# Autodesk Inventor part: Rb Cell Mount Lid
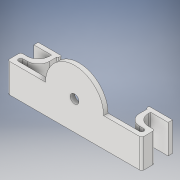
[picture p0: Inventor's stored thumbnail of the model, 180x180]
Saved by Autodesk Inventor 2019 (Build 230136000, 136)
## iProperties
Created: 2019-02
Part Number: Rb Cell Mount Lid
Material: PC/ABS Plastic
Document SubType Name: Modeling
Designer: Rydberg
Density: 0.357273 g/cm^3
Appearance: Smooth - White
Author: Rydberg
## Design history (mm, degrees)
sketch "Sketch1"
  geometry: L1 (0, 0)-(41, 0); L2 (41, 0)-(41, -13.2); L3 (41, -13.2)-(0, -13.2); L4 (0, -13.2)-(0, 0); C1 r 13.2 at (20.5, -13.2)
  constraints: 8 end point, 2 parallel, 1 centre point, 1 horizontal, 1 midpoint, 1 perpendicular
  dimensions: "d0" = 41 distance of L2.end L3.end; "d1" = 13.2 distance of L1.end L2.end; "d2" = 26.4 diameter of C1
extrude "Extrusion1" new body sketch "Sketch1" distance "d3" = 2; taper "d4" = 0 deg
sketch "Sketch2"
  geometry: L1 (41, 0)-(0, 0) reference; L2 (0, 0)-(-2, 0); L3 (-2, 0)-(-2, -13.2); L4 (-2, -13.2)-(0, -13.2); L5 (0, -13.2)-(0, 0); L6 (41, 0)-(43, 0); L7 (43, 0)-(43, -13.2); L8 (43, -13.2)-(41, -13.2); L9 (41, -13.2)-(41, 0)
  constraints: 16 end point, 4 parallel, 2 horizontal, 2 perpendicular, 1 point on line
  dimensions: "d5" = 2 distance of L4.end L3.end; "d6" = 2 distance of L8.end L7.end
extrude "Extrusion2" join sketch "Sketch2" distance "d7" = 12.5; taper "d8" = 0 deg
sketch "Sketch3"
  geometry: 1 further point
sketch "Sketch4"
  geometry: L1 (-2, -2)-(-2, 10.5) reference; L2 (-2, 10.5)-(-2, 12); L3 (-2, 12)-(1, 12); L4 (1, 12)-(0.3, 10.5); L5 (0, 0)-(0, 10.5) reference; L6 (0.3, 10.5)-(0, 10.5); L7 (43, 10.5)-(41, 10.5) reference; L8 (43, 10.5)-(43, 12); L9 (43, 12)-(40, 12); L10 (-2, 10.5)-(0, 10.5); L11 (43, 10.5)-(40.7, 10.5); L12 (40.7, 10.5)-(40, 12)
  constraints: 18 end point, 3 perpendicular, 2 vertical, 1 parallel, 1 point on line
  dimensions: "d9" = 1.5 distance of L1.end L2.end; "d10" = 3 distance of L2.end L3.end; "d11" = 0.3 distance of L4.end L5.end; "d12" = 1.5 distance of L7.start L8.end; "d13" = 3 distance of L8.end L9.end; "d14" = 2.3 distance of L7.start L11.end
extrude "Extrusion3" join sketch "Sketch4" stored distance "d15" = 8; taper "d16" = 0 deg
fillet "Fillet1" dims "d17" = 0.5
fillet "Fillet2" dims "d18" = 0.5
sketch "Sketch5"
  geometry: L1 (-1, 0)-(42, 0); L2 (42, 0)-(42, 1.316); L3 (42, 1.316)-(-1, 1.316); L4 (-1, 1.316)-(-1, 0); L5 (0, 0)-(0, 10.5) reference; L6 (41, 0)-(41, 10.5) reference
  constraints: 8 end point, 2 parallel, 1 horizontal, 1 perpendicular
  dimensions: "d19" = 1 distance between parallel lines of L5 L4; "d20" = 1 distance between parallel lines of L6 L2
extrude "Extrusion4" cut sketch "Sketch5" extent not by distance; stored distance "d21" = 8; taper "d22" = 0 deg
sketch "Sketch6"
  geometry: C1 r 2 at (20.5, -13.2); A1 r 13.2 centre (20.5, -13.2) between (7.3, -13.2) and (33.7, -13.2) reference; 1 further point
  constraints: 1 centre point, 1 coincident
  dimensions: "d23" = 4 diameter of C1
extrude "Extrusion5" cut sketch "Sketch6" distance "d24" = 8; taper "d25" = 0 deg
sketch "Sketch7"
  geometry: L1 (-43, 0)-(-41, 0) reference; L2 (-41, 0)-(-51, 0); L3 (-51, 0)-(-51, -6); L4 (-51, -6)-(-41, -6); L5 (-41, -6)-(-41, 0); L6 (0, 0)-(2, 0) reference; L7 (0, 0)-(10, 0); L8 (10, 0)-(10, -6); L9 (10, -6)-(0, -6); L10 (0, -6)-(0, 0); 1 further point
  constraints: 16 end point, 4 parallel, 2 horizontal, 2 perpendicular
  dimensions: "d26" = 10 distance of L4.end L3.end; "d27" = 6 distance of L3.end L2.end; "d28" = 10 distance of L8.end L9.end; "d29" = 6 distance of L7.end L8.end
extrude "Extrusion6" join sketch "Sketch7" stored distance "d30" = 1.7; taper "d31" = 0 deg
sketch "Sketch8"
  geometry: L1 (-49, 8.5)-(8, 8.5); L2 (8, 8.5)-(8, 10.5); L3 (8, 10.5)-(-49, 10.5); L4 (-49, 10.5)-(-49, 8.5); L5 (-51, 12.5)-(-51, 6.5) reference; L6 (-51, 6.5)-(-43, 6.5) reference; L7 (-51, 12.5)-(-33.7, 12.5) reference; L8 (10, 12.5)-(10, 6.5) reference; 3 further points
  constraints: 8 end point, 2 parallel, 1 horizontal, 1 perpendicular
  dimensions: "d32" = 2 distance between parallel lines of L5 L4; "d33" = 2 distance between parallel lines of L6 L1; "d34" = 2 distance between parallel lines of L7 L3; "d35" = 2 distance between parallel lines of L2 L8
extrude "Extrusion7" cut sketch "Sketch8" extent not by distance; stored distance "d36" = 1.7; taper "d37" = 0 deg
sketch "Sketch9"
  geometry: L1 (-40.785, -1.5)-(-42.5, -1.5) reference; L2 (-41, -1.5)-(-51, -1.5); L3 (-51, -1.5)-(-51, 0.5); L4 (-51, 0.5)-(-41, 0.5); L5 (-41, 0.5)-(-41, -1.5); L6 (0, -1.5)-(10, -1.5); L7 (10, -1.5)-(10, 0.5); L8 (10, 0.5)-(0, 0.5); L9 (0, 0.5)-(0, -1.5); 1 further point
  constraints: 16 end point, 4 parallel, 2 horizontal, 2 perpendicular, 1 point on line
  dimensions: "d38" = 2 distance of L2.end L3.end; "d39" = 2 distance of L7.end L6.end
extrude "Extrusion8" join sketch "Sketch9" stored distance "d40" = 1.7; taper "d41" = 0 deg
fillet "Fillet3" dims "d42" = 1
fillet "Fillet4" dims "d43" = 5
body "Solid1"
